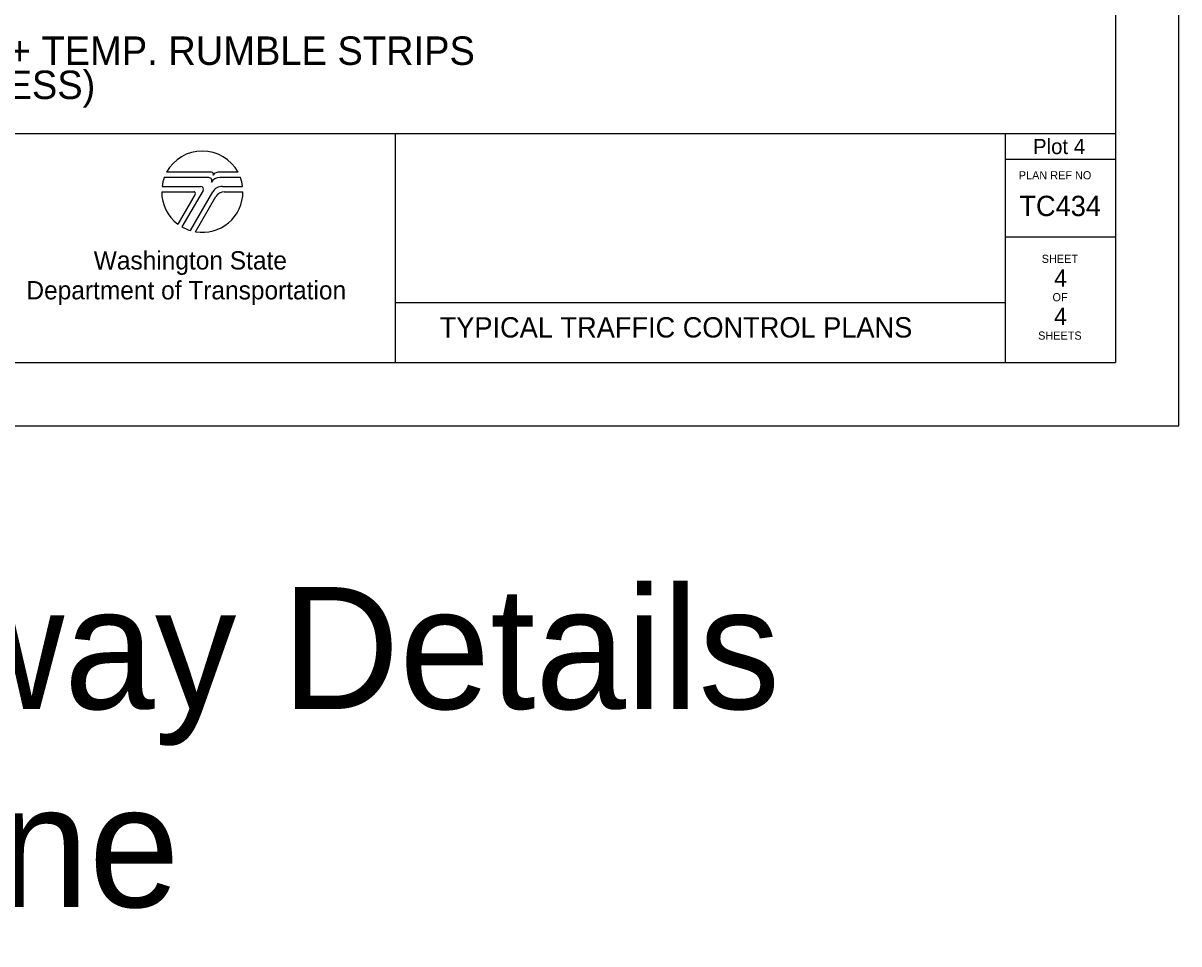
# Model space of a CAD drawing. Extents: x 99999.1 to 100095.7, y 99995 to 100010.7.
# Drawn here: x 100070.38 to 100076.06, y 99997.14 to 100001.67 of the extents above; entities that cross this region are included whole.
import ezdxf

# ---------------------------------------------------------------- set-up
doc = ezdxf.new("R2010")
doc.units = 0
for name, color, linetype in [('SH_DE_DetailHeading1Text', 7, 'Continuous'), ('SH_GI_PlotLimits', 7, 'Continuous'), ('SH_GI_SheetBorder', 7, 'Continuous'), ('SH_GI_SheetLocationText', 7, 'Continuous'), ('SH_GI_SheetTextInCells', 7, 'Continuous'), ('SH_GI_TitleBlockText', 7, 'Continuous'), ('SH_GI_WSDOTLogo', 7, 'Continuous')]:
    doc.layers.add(name, color=color, linetype=linetype)

msp = doc.modelspace()

# ---------------------------------------------------------------- linework, layer by layer
at = {"layer": 'SH_GI_PlotLimits'}
msp.add_lwpolyline([(100059.0625, 99999.6875), (100076.0625, 99999.6875), (100076.0625, 100010.6875), (100059.0625, 100010.6875)], close=True, dxfattribs=at)
at = {"layer": 'SH_GI_SheetBorder'}
for p, q in [((100075.75, 100010.375), (100075.75, 100000)), ((100060, 100001.1259), (100075.75, 100001.1259)), ((100072.2055, 100001.1259), (100072.2055, 100000)), ((100075.2079, 100001.1259), (100075.2079, 100000)), ((100075.2079, 100001.0008), (100075.75, 100001.0008)), ((100075.2079, 100000.6176), (100075.75, 100000.6176)), ((100072.2055, 100000.2955), (100075.2079, 100000.2955)), ((100060, 100000), (100075.75, 100000))]:
    msp.add_line(p, q, dxfattribs=at)
at = {"layer": 'SH_GI_WSDOTLogo'}
for p, q in [((100071.2894, 100000.9094), (100071.0697, 100000.9094)), ((100071.303, 100000.9354), (100071.0815, 100000.9354)), ((100071.433, 100000.9354), (100071.3351, 100000.9354)), ((100071.343, 100000.9094), (100071.3429, 100000.9094)), ((100071.4448, 100000.9094), (100071.343, 100000.9094)), ((100071.0572, 100000.84), (100071.2148, 100000.84)), ((100071.059, 100000.8661), (100071.2496, 100000.8661)), ((100071.261, 100000.8464), (100071.1567, 100000.6672)), ((100071.1989, 100000.6487), (100071.3089, 100000.839)), ((100071.3558, 100000.8661), (100071.4555, 100000.8661)), ((100071.3655, 100000.8394), (100071.4572, 100000.8394)), ((100071.222, 100000.8277), (100071.1364, 100000.6807)), ((100071.2244, 100000.6428), (100071.3242, 100000.8156))]:
    msp.add_line(p, q, dxfattribs=at)
for centre, radius, start, end in [((100071.2572, 100000.84), 0.2, 28.4787, 151.532), ((100071.2572, 100000.84), 0.2, 159.696, 172.5057), ((100071.2894, 100000.8946), 0.0148, 327.8418, 89.9985), ((100071.3429, 100000.861), 0.0484, 89.9953, 147.8238), ((100071.303, 100000.9263), 0.00903, 329.8742, 90.0033), ((100071.3352, 100000.9066), 0.0287, 90.0072, 148.1676), ((100071.2572, 100000.84), 0.2, 7.4943, 20.2941), ((100071.2572, 100000.84), 0.2, 179.9986, 232.8433), ((100071.2149, 100000.8318), 0.0082, 329.7436, 90), ((100071.2572, 100000.84), 0.2, 260.5455, 359.8086), ((100071.2497, 100000.853), 0.0131, 329.7683, 90), ((100071.3558, 100000.8119), 0.0542, 90, 149.9974), ((100071.3654, 100000.7918), 0.0476, 90, 150.0543), ((100071.2572, 100000.84), 0.2, 239.7929, 253.0448)]:
    msp.add_arc(centre, radius, start, end, dxfattribs=at)

# ---------------------------------------------------------------- texts
at = {"layer": 'SH_DE_DetailHeading1Text'}
for s, p in [('PILOT CAR OPERATION FOR ALTERNATING 1-LANE, 2-WAY TRAFFIC: AFAD-CONTROLLED + TEMP. RUMBLE STRIPS', (100062.1077, 100001.4639)), ('SEPARATED BICYCLE LANE STRATEGY (HIGHWAYS, 40 MPH OR LESS)', (100064.3016, 100001.2959))]:
    msp.add_text(s, height=0.14, rotation=360, dxfattribs=at).set_placement(p)
at = {"layer": 'SH_GI_SheetBorder'}
msp.add_text('PLAN REF NO', height=0.040032, dxfattribs=at).set_placement((100075.2747, 100000.9008))
at = {"layer": 'SH_GI_SheetLocationText'}
for s, height, p in [('Plot 4', 0.075, (100075.3447, 100001.025)), ('Access & Intersecting Roadway Details', 0.6, (100060.1422, 99998.2946)), ('Separated Bike Lane', 0.6, (100063.6511, 99997.3196))]:
    msp.add_text(s, height=height, dxfattribs=at).set_placement(p)
at = {"layer": 'SH_GI_SheetTextInCells'}
for s, height, p in [('Washington State', 0.090072, (100070.7229, 100000.4571)), ('SHEET', 0.04003, (100075.3877, 100000.4896)), ('Department of Transportation', 0.090072, (100070.3916, 100000.3101)), ('OF', 0.04003, (100075.4406, 100000.3008)), ('SHEETS', 0.04003, (100075.3698, 100000.112))]:
    msp.add_text(s, height=height, dxfattribs=at).set_placement(p)
at = {"layer": 'SH_GI_TitleBlockText'}
for s, height, p in [('TC434', 0.1, (100075.2776, 100000.72)), ('4', 0.085, (100075.4485, 100000.3723)), ('4', 0.085, (100075.4485, 100000.1843)), ('TYPICAL TRAFFIC CONTROL PLANS', 0.1, (100072.4251, 100000.1224))]:
    msp.add_text(s, height=height, dxfattribs=at).set_placement(p)

doc.saveas('drawing.dxf')
